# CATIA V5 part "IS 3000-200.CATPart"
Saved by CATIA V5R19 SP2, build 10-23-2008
Part number: IS 3000-200
Bounding box of the stored display mesh (mm): x -47.487 to 47.487, y -47.487 to 47.487, z 0 to 520
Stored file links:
  C:\Users\Bora\Desktop\3D Katı model\IS serisi\IS 3000\IS 3000-200.CATPart
  C:\Program Files\Dassault Systemes\B19\intel_a\reffiles\standard\MetricThickPitch.txt
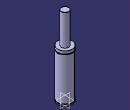
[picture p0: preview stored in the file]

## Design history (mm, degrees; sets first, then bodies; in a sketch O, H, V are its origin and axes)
Body1 (main body)
  Sketch1 on yz-plane, origin (0, 0, 0), H (0, 1, 0), V (0, 0, 1)
    point P1 (47.5, 298.5)
    point P2 (47.5, 293.5)
    point P5 (25, 519)
    point P7 (25, 519)
    point P12 (47.5, 293.5)
    point P13 (47.5, 298.5)
    arc A1 centre (47.5, 296) radius 2.5 from (47.5, 298.5) to (47.5, 293.5) ccw
    line L1 (47.5, 0) -> (47.5, 8)
    line L2 (25, 519) -> (25, 317)
    arc A2 centre (24, 519) radius 1 from (25, 519) to (24, 520) ccw
    line L3 (43.5, 13) -> (43.5, 8)
    line L4 (47.5, 13) -> (47.5, 293.5)
    line L5 (47.5, 298.5) -> (47.5, 317)
    line L6 (24, 520) -> (0, 520)
    point P15 (0, 520)
    line L7 (25, 317) -> (47.5, 317)
    line L8 (0, 0) -> (47.5, 0)
    line L9 (43.5, 13) -> (47.5, 13)
    line L10 (43.5, 8) -> (47.5, 8)
    coincidence: P15 V, P1 P13, P2 P12, P5 P7
    tangency: L6 A2
    horizontal: L7 H, L8 H, L9 H, L10 H
  Shaft1: profile Sketch1, axis Sketch1.V, angle 360
  Sketch2 on face of Shaft1 from Sketch1.L8, origin (0, 0, 0), H (1, 0, 0), V (0, -1, 0)
    point P1 (30, 0)
    distance P1 V = 30
  Hole1: placed by Sketch2, at (30, 0, 0) direction (0, 0, 1), diameter 6.647, depth 13, threaded "M8", thread diameter 8, thread depth 13, pitch 1.25
  CircPattern1: of Hole1, instances 4, angular step 90, axis from xy-plane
